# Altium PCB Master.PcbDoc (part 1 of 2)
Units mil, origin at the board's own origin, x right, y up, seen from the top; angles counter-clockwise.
Board outline 11420.03 x 8220.01 mil, 2 copper layers (Top Layer, Bottom Layer); 224 components, 0 nets, 1169 pads, 54 vias.
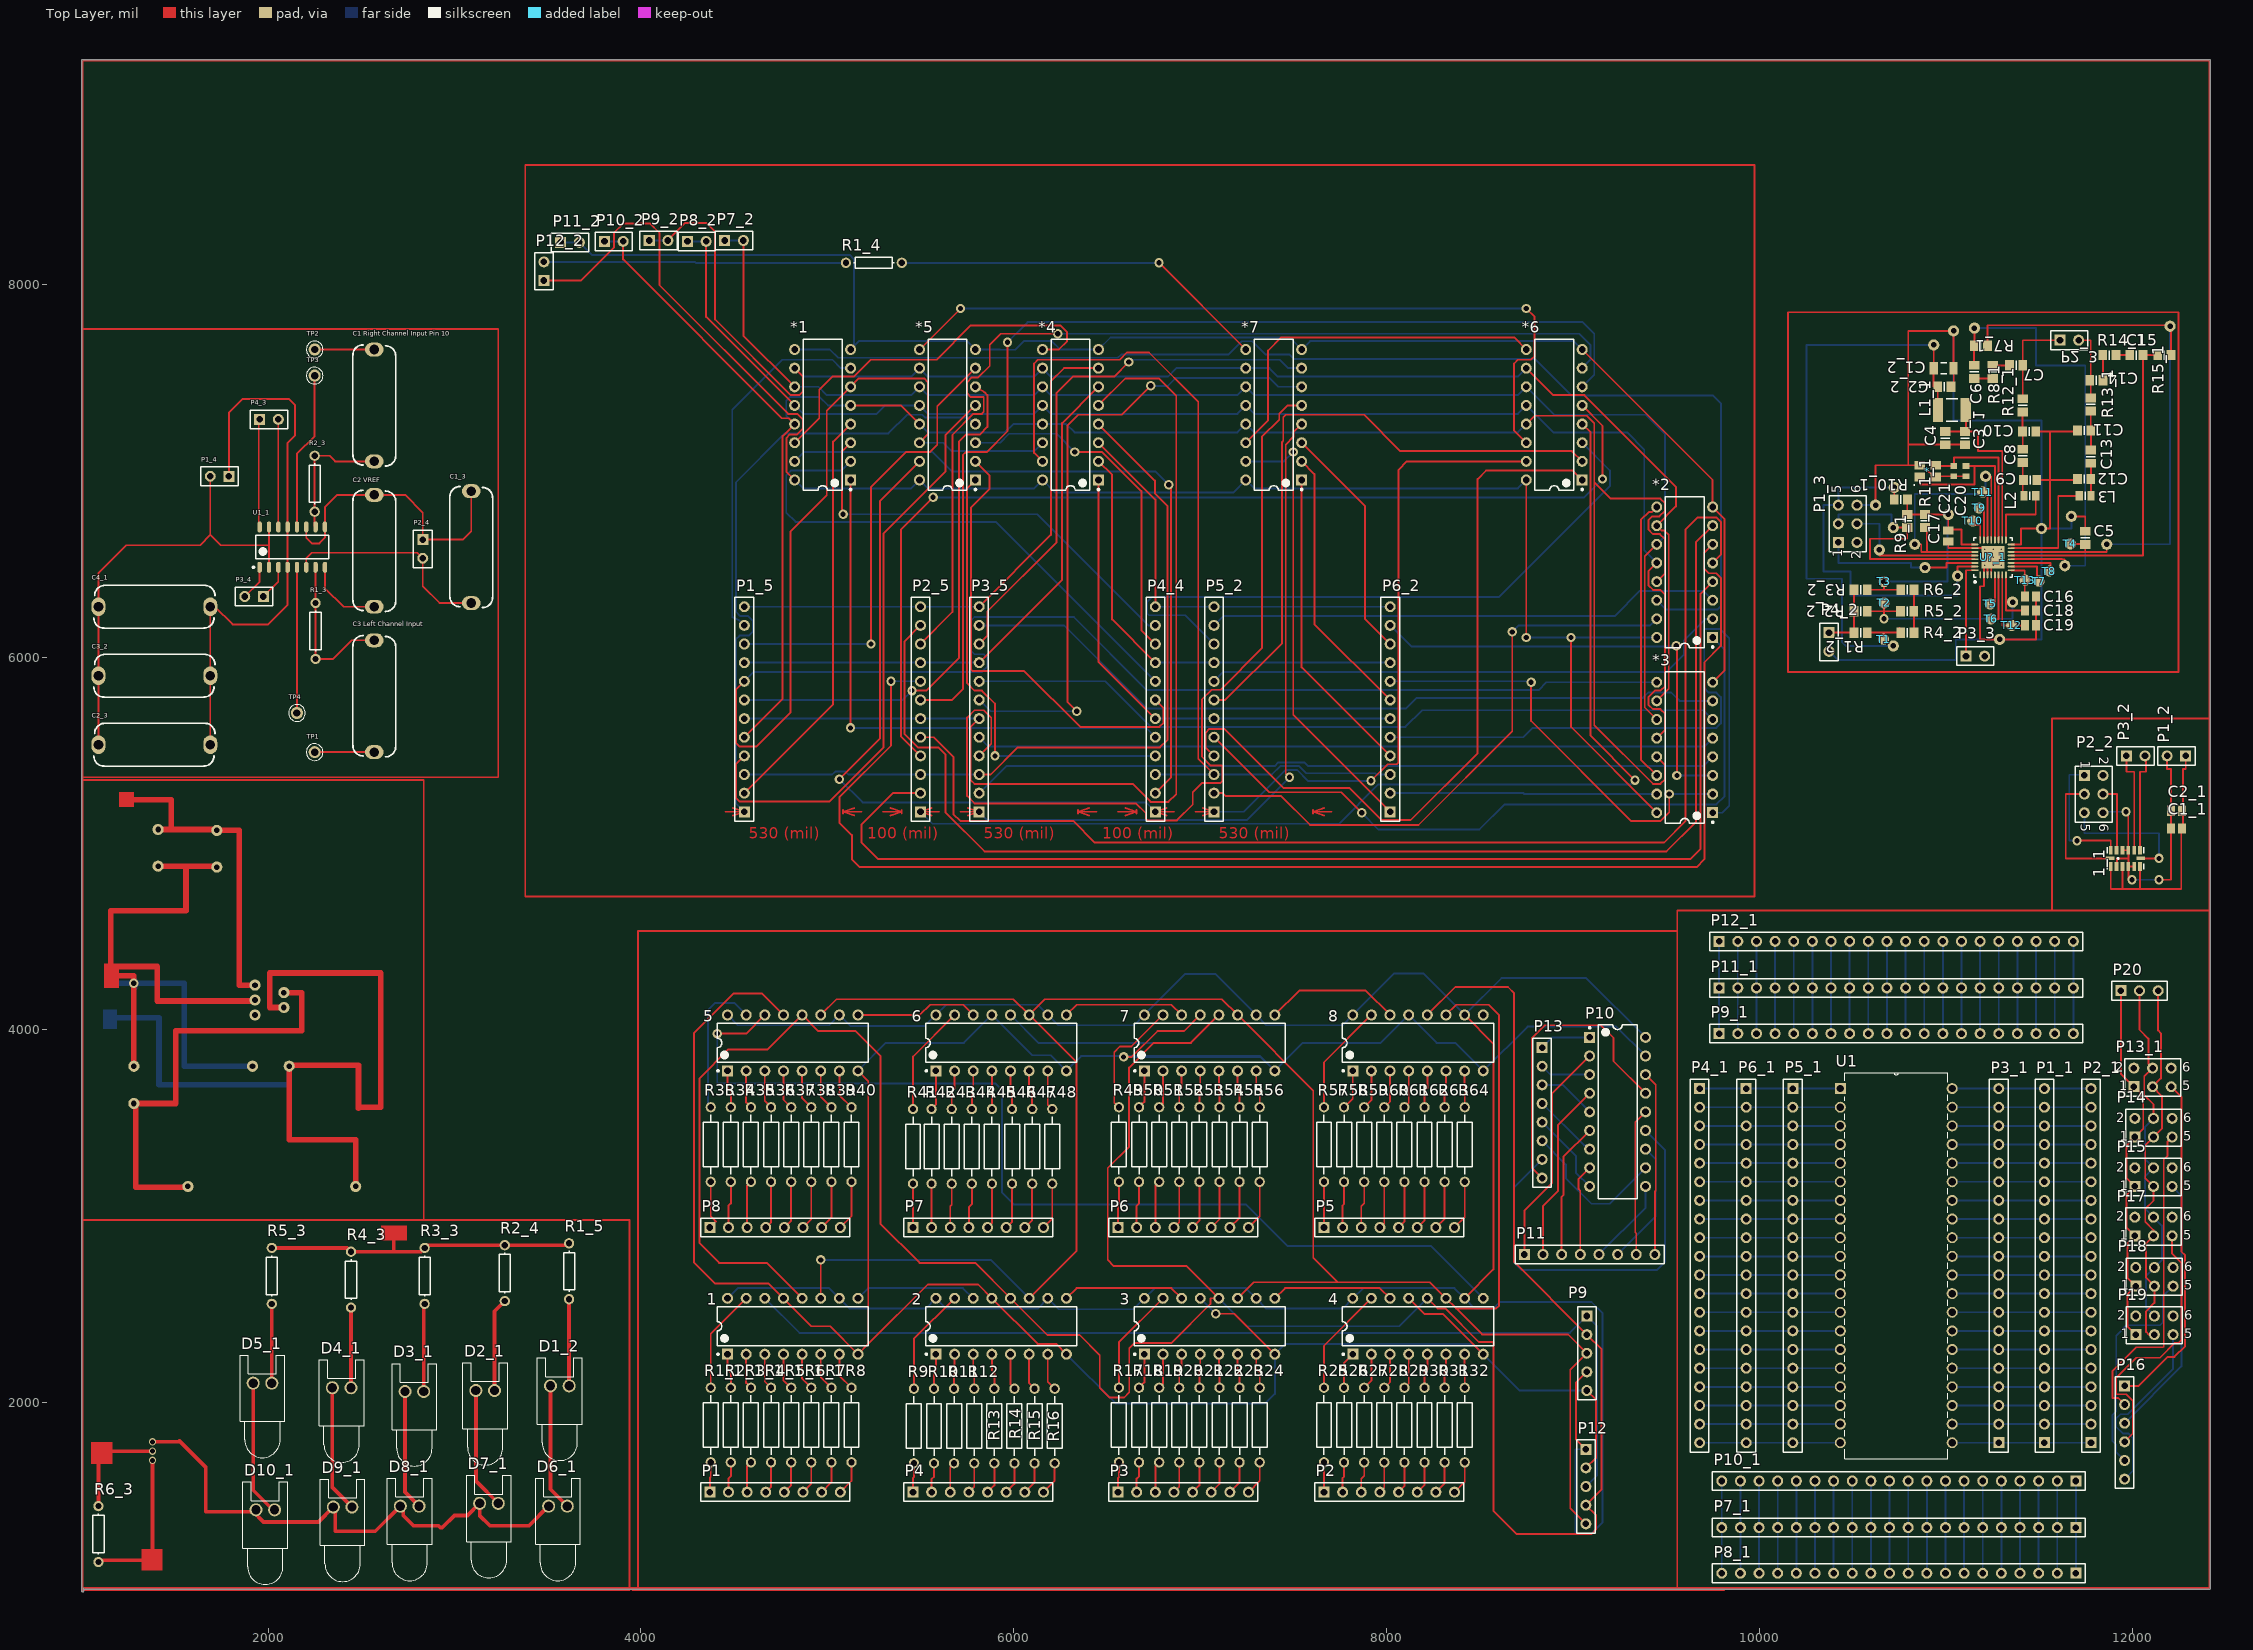
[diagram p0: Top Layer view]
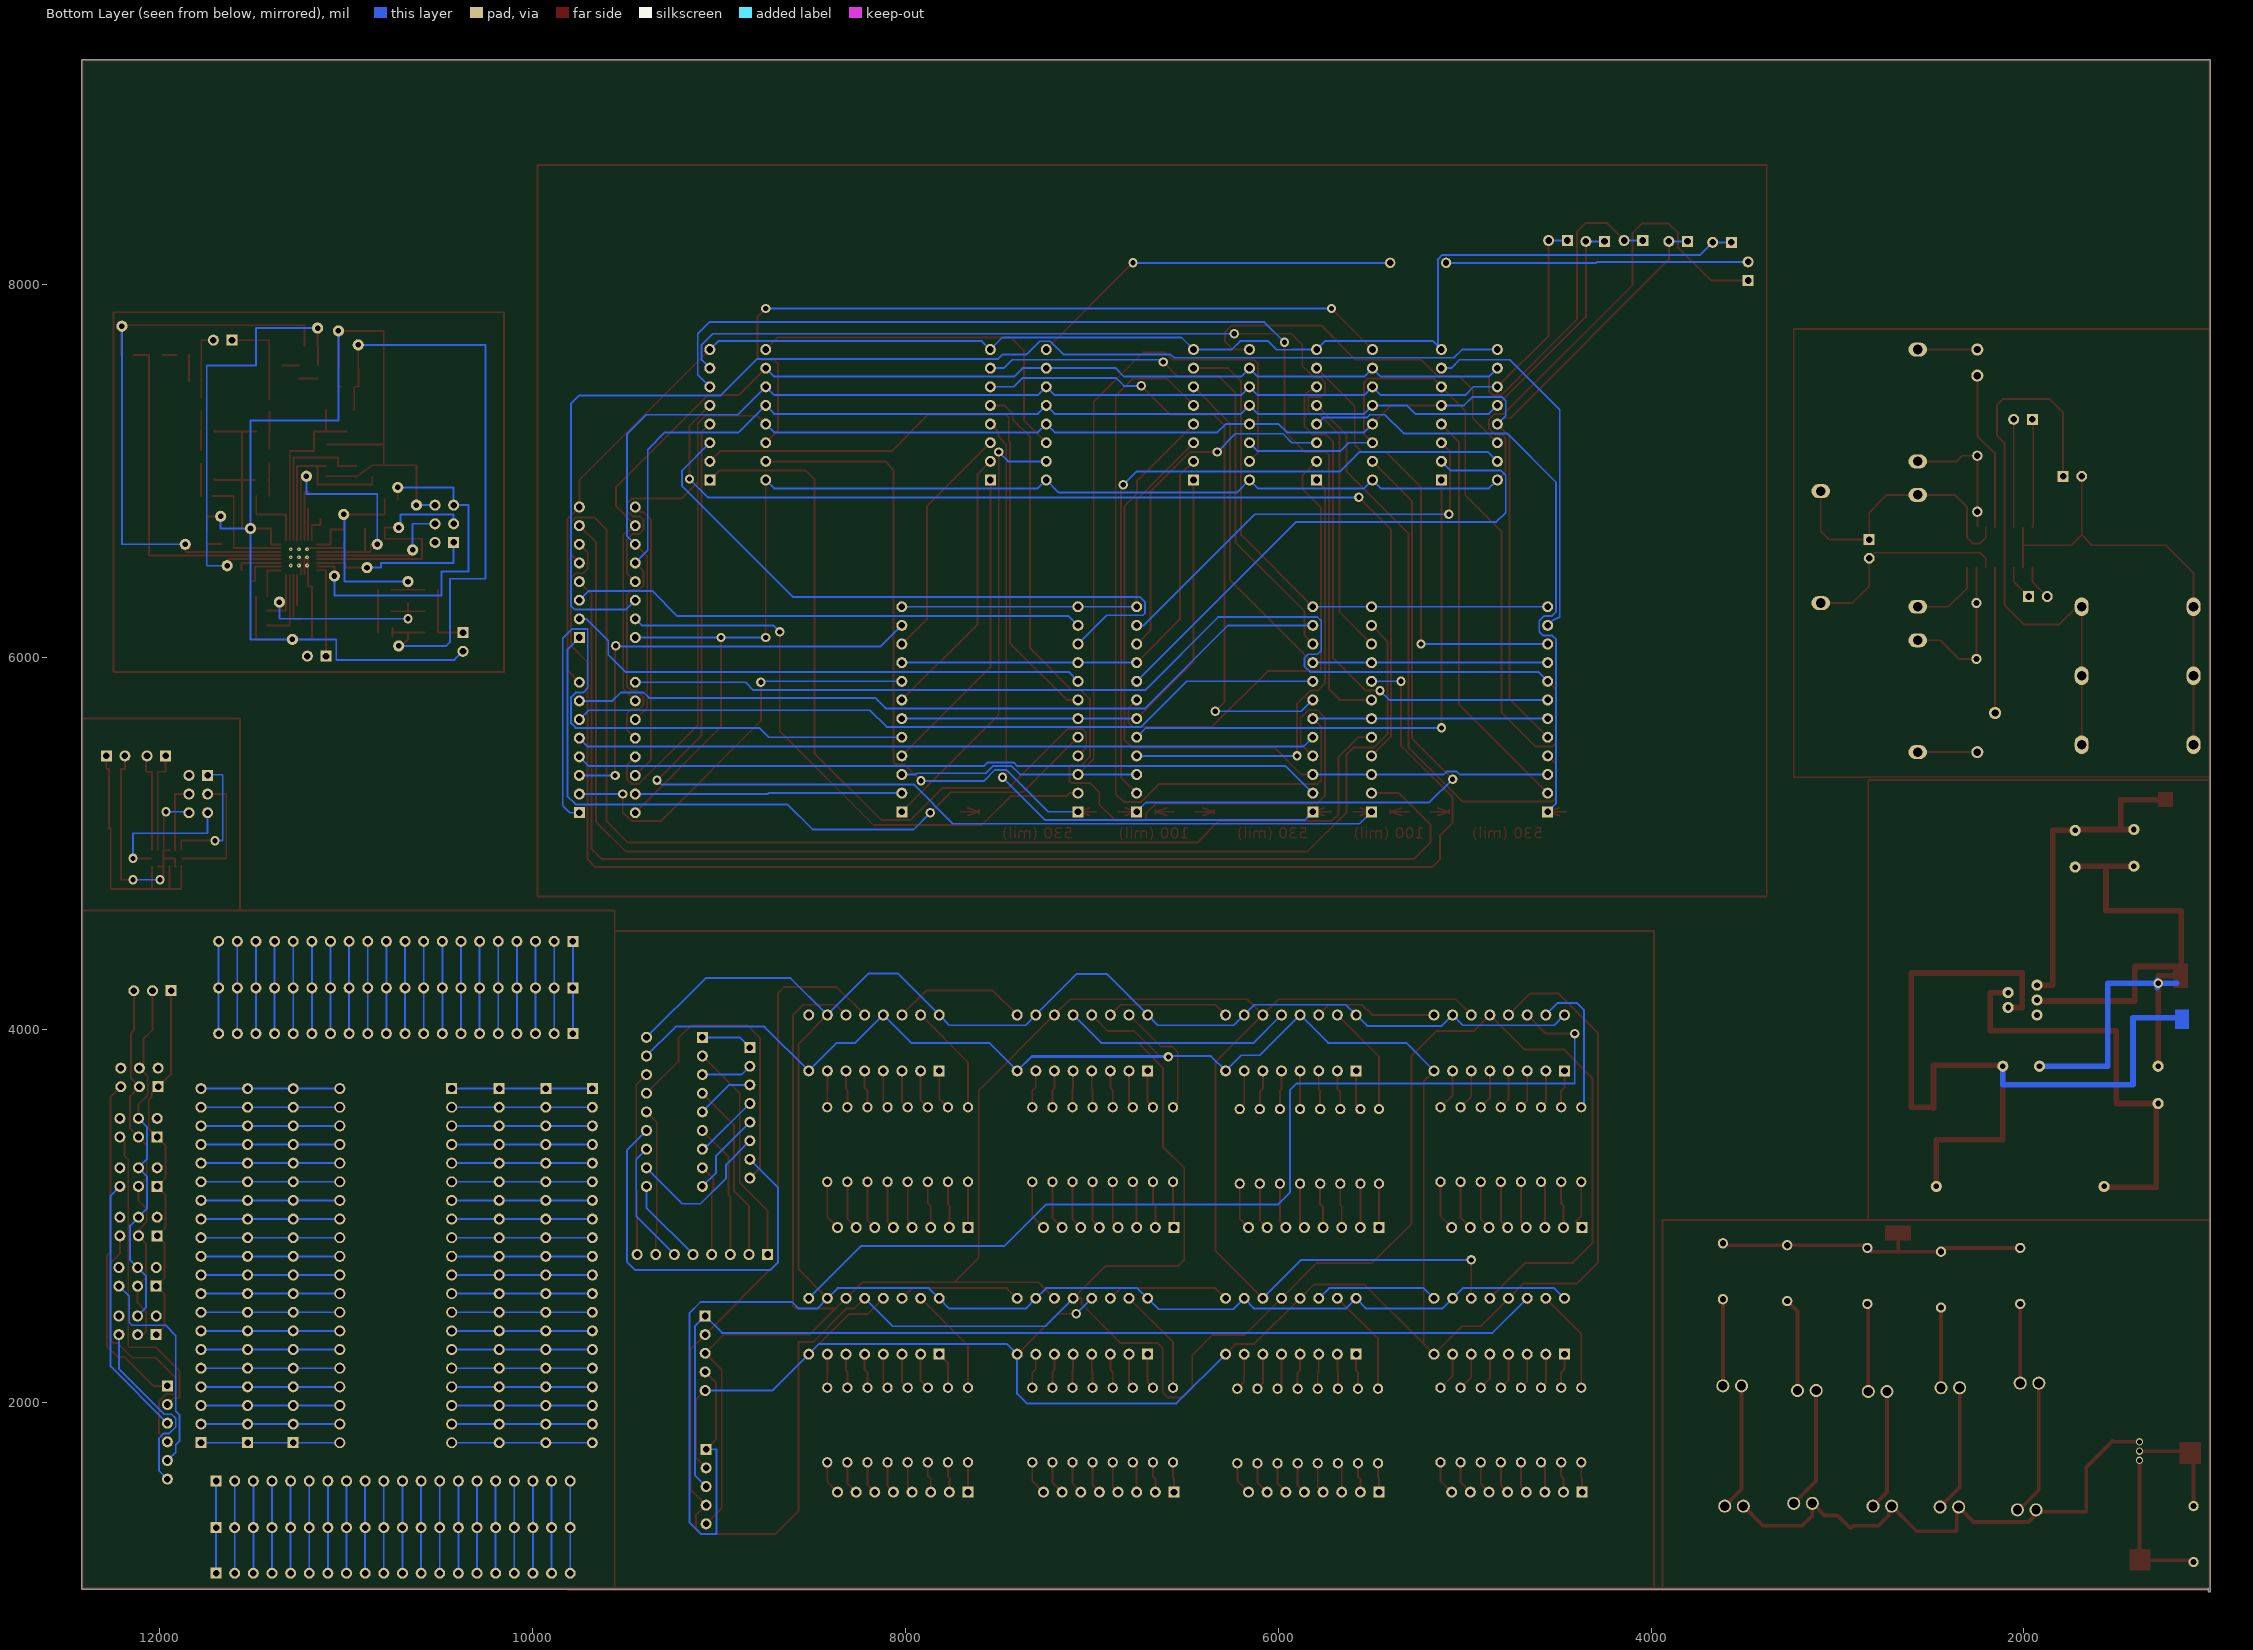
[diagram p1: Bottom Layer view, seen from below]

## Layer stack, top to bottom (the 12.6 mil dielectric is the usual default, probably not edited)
Top Solder: solder mask 0.4, Solder Resist, Dk 3.5
Top Layer: signal copper 1.4
Dielectric 1: dielectric 12.6, FR-4, Dk 4.8
Bottom Layer: signal copper 1.4
Bottom Solder: solder mask 0.4, Solder Resist, Dk 3.5

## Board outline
999.99,990 999.99,9200 cw(c1005,9200) 1005,9205.01 12415,9205.01 cw(c12415,9200) 12420.01,9200 12420.01,1005 cw(c12415,1005) 12415,999.99 1015,999.99 cw(c1015,1005) 1010.01,1004.45 1010.01,990 cw(c1005,990)

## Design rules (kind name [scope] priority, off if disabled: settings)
Clearance [All] p1: gap=10
PolygonConnect [All] p1: connectstyle=Relief reliefconductorwidth=10 reliefentries=4 polygonreliefangle="90 Angle" airgapwidth=10
RoomDefinition IRLED_1 [InComponentClass('IRLED')] p1: confinementstyle=ConfineIn formatcopy=TRUE lockcomponents=FALSE outline 1015,2980 3940,2980 3940,995 1015,995
RoomDefinition "Senior design LED matrix 3.0" [InComponentClass('Senior design LED matrix 3.0')] p2: confinementstyle=ConfineIn formatcopy=TRUE lockcomponents=FALSE outline 3385,4735 9985,4735 9985,8640.01 3385,8640.01
RoomDefinition "PAM 8403 Breakout Board" [InComponentClass('PAM 8403 Breakout Board')] p3: confinementstyle=ConfineIn formatcopy=TRUE lockcomponents=FALSE outline 3235,5360 3235,7760 1035,7760 1035,5360
RoomDefinition MCU [InComponentClass('MCU')] p4: confinementstyle=ConfineIn formatcopy=TRUE lockcomponents=FALSE outline 9610,1020 12415,1020 12415,4640 9610,4640
RoomDefinition CLRC663Design [InComponentClass('CLRC663Design')] p5: confinementstyle=ConfineIn formatcopy=TRUE lockcomponents=FALSE outline 12250.12,5920 12250.12,7850 10155,7850 10155,5920
RoomDefinition LEDCube [InComponentClass('LEDCube')] p6: confinementstyle=ConfineIn formatcopy=TRUE lockcomponents=FALSE outline 3985,995 9810,995 9810,4530 3985,4530
RoutingVias [All] p1: holewidth=28 width=50 viastyle="Through Hole" minholewidth=28 minwidth=50 maxholewidth=28 maxwidth=50
SolderMaskExpansion [All] p1: expansion=4
Width [All] p1: maxlimit=10 minlimit=10 preferedwidth=10
30 further rules are at their usual default settings.

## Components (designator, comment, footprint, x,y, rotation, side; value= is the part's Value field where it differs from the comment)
1 "74HC595" DIP-16 4815,2410 r90 top
1_1 "LIS302DL" LGA14_LIS302DL(Primary) 11964.25,4920 r180 top (schematic designator 1)
2 "74HC595" DIP-16 5933.1,2410 r90 top
3 "74HC595" DIP-16 7051.19,2410 r90 top
4 "74HC595" DIP-16 8169.29,2410 r90 top
5 "74HC595" DIP-16 4815,3930 r90 top
6 "74HC595" DIP-16 5933.1,3930 r90 top
7 "74HC595" DIP-16 7051.19,3930 r90 top
8 "74HC595" DIP-16 8169.29,3930 r90 top
* "Crystal" DFN220P355X80-4N 10904.25,6997.44 r0 top
*1 "Red_1" DIP-16 4975,7300 r180 top
*2 "Red_2" DIP-16 9600,6455 r180 top
*3 "Red_3" DIP-16 9600,5515 r180 top
*4 "Ground" DIP-16 6305,7300 r180 top
*5 "Green_1" DIP-16 5645,7300 r180 top
*6 "Green_2" DIP-16 8900,7300 r180 top
*7 "Green_3" DIP-16 7395,7300 r180 top
"C1 Right Channel Input Pin 10" "Cap" "Rad .6" 2570,7350 r90 top
C1_1 "Cap" C0805 12239.25,5080 r180 top (schematic designator C1)
C1_2 "Cap" C1206 10989.25,7550 r0 top (schematic designator C1)
C1_3 "Cap" "Rad .6" 3090,6590 r270 top (schematic designator C1)
"C2 VREF" "Cap" "Rad .6" 2570,6570 r90 top
C2_1 "Cap" C0805 12239.25,5175 r180 top (schematic designator C2)
C2_2 "Cap" 6-0805_N 10993.39,7450 r0 top (schematic designator C2)
C2_3 "Cap" "Rad .6" 1390,5530 r180 top (schematic designator C2)
"C3 Left Channel Input" "Cap" "Rad .6" 2570,5790 r270 top
C3_1 "Cap" 6-0805_N 11103.39,7175 r270 top (schematic designator C3)
C3_2 "Cap" "Rad .6" 1390,5900 r180 top (schematic designator C3)
C4 "Cap" 6-0805_N 10998.39,7175 r270 top
C4_1 "Cap" "Rad .6" 1390,6270 r180 top (schematic designator C4)
C5 "Cap" 6-0805_N 11749.25,6640 r90 top
C6 "Cap" 6-0805_N 11153.39,7530 r90 top
C7 "Cap" 6-0805_N 11378.39,7565 r0 top
C8 "Cap" 6-0805_N 11413.39,7080 r270 top
C9 "Cap" 6-0805_N 11453.39,6950 r180 top
C10 "Cap" 6-0805_N 11448.39,7210 r0 top
C11 "Cap" 6-0805_N 11743.39,7215 r0 top
C12 "Cap" 6-0805_N 11743.39,6955 r180 top
C13 "Cap" 6-0805_N 11778.39,7075 r270 top
C14 "Cap" 6-0805_N 11808.39,7485 r0 top
C15 "Cap" 6-0805_N 12023.39,7620 r0 top
C16 "Cap Pol3" C0805 11454.25,6325 r0 top
C17 "Cap Pol3" C0805 11014.25,6650 r270 top
C18 "Cap Pol3" C0805 11454.25,6250 r0 top
C19 "Cap Pol3" C0805 11454.25,6170 r0 top
C20 "Cap Semi" 1608[0603] 11109.25,6997.44 r90 top
C21 "Cap Semi" 1608[0603] 11044.25,6997.44 r90 top
D1_2 "LED0" LED-0 3565,2090 r0 top (schematic designator D1)
D2_1 "LED0" LED-0 3165,2065 r0 top (schematic designator D2)
D3_1 "LED0" LED-0 2785,2060 r0 top (schematic designator D3)
D4_1 "LED0" LED-0 2395,2080 r0 top (schematic designator D4)
D5_1 "LED0" LED-0 1970,2105 r0 top (schematic designator D5)
D6_1 "LED0" LED-0 3555,1445 r0 top (schematic designator D6)
D7_1 "LED0" LED-0 3185,1460 r0 top (schematic designator D7)
D8_1 "LED0" LED-0 2760,1445 r0 top (schematic designator D8)
D9_1 "LED0" LED-0 2400,1440 r0 top (schematic designator D9)
D10_1 "LED0" LED-0 1985,1425 r0 top (schematic designator D10)
L1_1 "Inductor" INDC4532 11033.39,7325 r180 top (schematic designator L1)
L2 "Inductor" 6-0805_L 11451.89,6865 r180 top
L3 "Inductor" 6-0805_L 11748.39,6865 r0 top
P1 "Header 8" HDR1X8 4370,1520 r0 top
P1_1 "Header 20" HDR1X20 11530,1785 r90 top (schematic designator P1)
P1_2 "Power" HDR1X2 12287.99,5470 r180 top (schematic designator P1)
P1_3 "SPI" HDR2X3#1 10424.25,6615 r90 top (schematic designator P1)
P1_4 "Header 2" HDR1X2 1790,6970 r180 top (schematic designator P1)
P1_5 "Header 12" HDR1X12 4555,5170 r90 top (schematic designator P1)
P2 "Header 8" HDR1X8 7665,1520 r0 top
P2_1 "Header 20" HDR1X20 11780,1785 r90 top (schematic designator P2)
P2_2 "SPI Header" HDR2X3#2 11744.25,5365 r270 top (schematic designator P2)
P2_3 "Header 2" HDR1X2 11613.39,7700 r0 top (schematic designator P2)
P2_4 "Header 2" HDR1X2 2830,6630 r270 top (schematic designator P2)
P2_5 "Header 12" HDR1X12 5500,5170 r90 top (schematic designator P2)
P3 "Header 8" HDR1X8 6560,1520 r0 top
P3_1 "Header 20" HDR1X20 11285,1785 r90 top (schematic designator P3)
P3_2 "Interrupt" HDR1X2 11969.25,5470 r0 top (schematic designator P3)
P3_3 "Interrupt" HDR1X2 11109.25,6005 r0 top (schematic designator P3)
P3_4 "Header 2" HDR1X2 1975,6325 r180 top (schematic designator P3)
P3_5 "Header 12" HDR1X12 5815,5170 r90 top (schematic designator P3)
P4 "Header 8" HDR1X8 5460,1520 r0 top
P4_1 "Header 20" HDR1X20 9680,3685 r270 top (schematic designator P4)
P4_2 "Power" HDR1X2 10374.25,6130.87 r270 top (schematic designator P4)
P4_3 "Header 2" HDR1X2 1955,7275 r0 top (schematic designator P4)
P4_4 "Header 12" HDR1X12 6760,5170 r90 top (schematic designator P4)
P5 "Header 8" HDR1X8 7665,2940 r0 top
P5_1 "Header 20" HDR1X20 10180,3685 r270 top (schematic designator P5)
P5_2 "Header 12" HDR1X12 7075,5170 r90 top (schematic designator P5)
P6 "Header 8" HDR1X8 6560,2940 r0 top
P6_1 "Header 20" HDR1X20 9930,3685 r270 top (schematic designator P6)
P6_2 "Header 12" HDR1X12 8020,5170 r90 top (schematic designator P6)
P7 "Header 8" HDR1X8 5460,2940 r0 top
P7_1 "Header 20" HDR1X20 11699,1330 r180 top (schematic designator P7)
P7_2 "11" HDR1X2 4450,8235 r0 top (schematic designator P7)
P8 "Header 8" HDR1X8 4370,2940 r0 top
P8_1 "Header 20" HDR1X20 11699,1085 r180 top (schematic designator P8)
P8_2 "12" HDR1X2 4250,8230 r0 top (schematic designator P8)
P9 "Header 5" HDR1X5 9075,2465 r270 top
P9_1 "Header 20" HDR1X20 9785,3980 r0 top (schematic designator P9)
P9_2 "10" HDR1X2 4045,8235 r0 top (schematic designator P9)
P10 "Darlinton transistorLeftToAVR" DIP-18 9240,3560 r0 top
P10_1 "Header 20" HDR1X20 11699,1580 r180 top (schematic designator P10)
P10_2 "13" HDR1X2 3805,8230 r0 top (schematic designator P10)
P11 "Cube Layer" HDR1X8 8740,2795 r0 top
P11_1 "Header 20" HDR1X20 9785,4225 r0 top (schematic designator P11)
P11_2 "Ground 8" HDR1X2 3570,8225 r0 top (schematic designator P11)
P12 "Matrix" HDR1X5 9070,1750 r270 top
P12_1 "Header 20" HDR1X20 9785,4475 r0 top (schematic designator P12)
P12_2 "1 (Power) 2 (Ground)" HDR1X2 3480,8020 r90 top (schematic designator P12)
P13 "AVR" HDR1X8 8835,3905 r270 top
P13_1 "Header 3X2" HDR2X3#2 12010,3695 r0 top (schematic designator P13)
P14 "Header 3X2" HDR2X3#2 12015,3425 r0 top
P15 "Header 3X2" HDR2X3#2 12015,3160 r0 top
P16 "Header 6" HDR1X6 11960,2090 r270 top
P17 "Header 3X2" HDR2X3#2 12015,2895 r0 top
P18 "Header 3X2" HDR2X3#2 12020,2625 r0 top
P19 "Header 3X2" HDR2X3#2 12020,2365 r0 top
P20 "Header 3" HDR1X3 11940,4210 r0 top
R1_1 "Res2" AXIAL-0.4 4374.88,1880 r270 top (schematic designator R1)
R1_2 "0R DNP" 6-0805_N 10544.25,6130.87 r180 top (schematic designator R1)
R1_3 "Res1" AXIAL-0.3 2255,6140 r90 top (schematic designator R1)
R1_4 "Res1" AXIAL-0.3 5250,8115 r180 top (schematic designator R1)
R1_5 "Res1" AXIAL-0.3 3615,2705 r90 top (schematic designator R1)
R2_1 "Res2" AXIAL-0.4 4482.76,1880 r270 top (schematic designator R2)
R2_2 "0R DNP" 6-0805_N 10544.25,6245.87 r180 top (schematic designator R2)
R2_3 "Res1" AXIAL-0.3 2250,6930 r270 top (schematic designator R2)
R2_4 "Res1" AXIAL-0.3 3270,2695 r90 top (schematic designator R2)
R3_1 "Res2" AXIAL-0.4 4590.63,1880 r270 top (schematic designator R3)
R3_2 "0R DNP" 6-0805_N 10544.25,6360.87 r180 top (schematic designator R3)
R3_3 "Res1" AXIAL-0.3 2840,2680 r90 top (schematic designator R3)
R4_1 "Res2" AXIAL-0.4 4698.5,1880 r270 top (schematic designator R4)
R4_2 "0R DNP" 6-0805_N 10794.25,6130.87 r180 top (schematic designator R4)
R4_3 "Res1" AXIAL-0.3 2445,2660 r90 top (schematic designator R4)
R5_1 "Res2" AXIAL-0.4 4806.38,1880 r270 top (schematic designator R5)
R5_2 "0R" 6-0805_N 10793.82,6245.87 r180 top (schematic designator R5)
R5_3 "Res1" AXIAL-0.3 2020,2680 r90 top (schematic designator R5)
R6_1 "Res2" AXIAL-0.4 4914.25,1880 r270 top (schematic designator R6)
R6_2 "0R" 6-0805_N 10794.25,6360.87 r180 top (schematic designator R6)
R6_3 "Res1" AXIAL-0.3 1090,1295 r90 top (schematic designator R6)
R7 "Res2" AXIAL-0.4 5022.13,1880 r270 top
R7_1 "Res3" 6-0805_N 11188.39,7670 r0 top (schematic designator R7)
R8 "Res2" AXIAL-0.4 5130,1880 r270 top
R8_1 "Res3" 6-0805_N 11253.39,7530 r90 top (schematic designator R8)
R9 "Res2" AXIAL-0.4 5464.88,1875 r270 top
R9_1 "Res3" 6-0805_N 10794.25,6730 r90 top (schematic designator R9)
R10 "Res2" AXIAL-0.4 5572.76,1875 r270 top
R10_1 "Res3" 6-0805_N 10759.25,6845 r0 top (schematic designator R10)
R11 "Res2" AXIAL-0.4 5680.63,1875 r270 top
R11_1 "Res3" 6-0805_N 10889.25,6730 r90 top (schematic designator R11)
R12 "Res2" AXIAL-0.4 5788.5,1875 r270 top
R12_1 "Res3" 6-0805_N 11413.39,7350 r90 top (schematic designator R12)
R13 "Res2" AXIAL-0.4 5896.38,1875 r270 top
R13_1 "Res3" 6-0805_N 11778.39,7355 r90 top (schematic designator R13)
R14 "Res2" AXIAL-0.4 6004.25,1875 r270 top
R14_1 "Res3" 6-0805_N 11878.39,7620 r180 top (schematic designator R14)
R15 "Res2" AXIAL-0.4 6112.13,1875 r270 top
R15_1 "Res3" 6-0805_N 12173.39,7620 r0 top (schematic designator R15)
R16 "Res2" AXIAL-0.4 6220,1875 r270 top
R17 "Res2" AXIAL-0.4 6564.88,1880 r270 top
R18 "Res2" AXIAL-0.4 6672.76,1880 r270 top
R19 "Res2" AXIAL-0.4 6780.63,1880 r270 top
R20 "Res2" AXIAL-0.4 6888.5,1880 r270 top
R21 "Res2" AXIAL-0.4 6996.38,1880 r270 top
R22 "Res2" AXIAL-0.4 7104.25,1880 r270 top
R23 "Res2" AXIAL-0.4 7212.13,1880 r270 top
R24 "Res2" AXIAL-0.4 7320,1880 r270 top
R25 "Res2" AXIAL-0.4 7664.88,1880 r270 top
R26 "Res2" AXIAL-0.4 7772.76,1880 r270 top
R27 "Res2" AXIAL-0.4 7880.63,1880 r270 top
R28 "Res2" AXIAL-0.4 7988.5,1880 r270 top
R29 "Res2" AXIAL-0.4 8096.38,1880 r270 top
R30 "Res2" AXIAL-0.4 8204.25,1880 r270 top
R31 "Res2" AXIAL-0.4 8312.13,1880 r270 top
R32 "Res2" AXIAL-0.4 8420,1880 r270 top
R33 "Res2" AXIAL-0.4 4374.88,3385 r90 top
R34 "Res2" AXIAL-0.4 4482.76,3385 r90 top
R35 "Res2" AXIAL-0.4 4590.63,3385 r90 top
R36 "Res2" AXIAL-0.4 4698.5,3385 r90 top
R37 "Res2" AXIAL-0.4 4806.38,3385 r90 top
R38 "Res2" AXIAL-0.4 4914.25,3385 r90 top
R39 "Res2" AXIAL-0.4 5022.13,3385 r90 top
R40 "Res2" AXIAL-0.4 5130,3385 r90 top
R41 "Res2" AXIAL-0.4 5460,3375 r90 top
R42 "Res2" AXIAL-0.4 5559.88,3375 r90 top
R43 "Res2" AXIAL-0.4 5667.76,3375 r90 top
R44 "Res2" AXIAL-0.4 5775.63,3375 r90 top
R45 "Res2" AXIAL-0.4 5883.5,3375 r90 top
R46 "Res2" AXIAL-0.4 5991.38,3375 r90 top
R47 "Res2" AXIAL-0.4 6099.25,3375 r90 top
R48 "Res2" AXIAL-0.4 6207.13,3375 r90 top
R49 "Res2" AXIAL-0.4 6564.88,3385 r90 top
R50 "Res2" AXIAL-0.4 6672.76,3385 r90 top
R51 "Res2" AXIAL-0.4 6780.63,3385 r90 top
R52 "Res2" AXIAL-0.4 6888.5,3385 r90 top
R53 "Res2" AXIAL-0.4 6996.38,3385 r90 top
R54 "Res2" AXIAL-0.4 7104.25,3385 r90 top
R55 "Res2" AXIAL-0.4 7212.13,3385 r90 top
R56 "Res2" AXIAL-0.4 7320,3385 r90 top
R57 "Res2" AXIAL-0.4 7664.88,3385 r90 top
R58 "Res2" AXIAL-0.4 7772.76,3385 r90 top
R59 "Res2" AXIAL-0.4 7880.63,3385 r90 top
R60 "Res2" AXIAL-0.4 7988.5,3385 r90 top
R61 "Res2" AXIAL-0.4 8096.38,3385 r90 top
R62 "Res2" AXIAL-0.4 8204.25,3385 r90 top
R63 "Res2" AXIAL-0.4 8312.13,3385 r90 top
R64 "Res2" AXIAL-0.4 8420,3385 r90 top
T1 "TVDD" PCBComponent_1 60281.75,55780.87 r0 top
T2 "VDD" PCBComponent_1 60284.68,55975.87 r0 top
T3 "PVDD" PCBComponent_1 60284.68,56090.87 r0 top
T4 "VMID" PCBComponent_1 -37945.75,-43077.56 r180 top
T5 "SIGIN" PCBComponent_1 -38375.75,-43400 r180 top
T6 "SIGOUT" PCBComponent_1 60928.39,-43410.43 r270 top
T7 "AUX1" PCBComponent_1 -38184.02,56022.44 r90 top
T8 "AUX2" PCBComponent_1 -38058.19,-43223.27 r180 top
T9 "SCL2" PCBComponent_1 -38504.88,56415 r90 top
T10 "SDA2" PCBComponent_1 -38469.88,-42955 r180 top locked
T11 "CLCKOUT" PCBComponent_1 -38485.75,56500 r90 top
T12 "DVDD" PCBComponent_1 -38330.75,55785 r90 top
T13 "AVDD" PCBComponent_1 -38189.02,-43272.13 r180 top locked
TP1 "TESTPOINT" "THROUGH HOLE TP" 2250,5490 r90 top
TP2 "TESTPOINT" "THROUGH HOLE TP" 2250,7650 r90 top
TP3 "TESTPOINT" "THROUGH HOLE TP" 2250,7510 r90 top
TP4 "TESTPOINT" "THROUGH HOLE TP" 2155,5700 r90 top
U1 "ATMEGA1284P-PU" DIP254P1524X483-40_ATMEGA1284P-PU(Primary) 11035,1785 r0 top
U1_1 "PAM8403" SOP127P600X175-16N 2130,6590 r90 top (schematic designator U1)
U?_1 "CLRC663" QFN50P500X500X100_HS-33N 11254.25,6535 r90 top (schematic designator U?)

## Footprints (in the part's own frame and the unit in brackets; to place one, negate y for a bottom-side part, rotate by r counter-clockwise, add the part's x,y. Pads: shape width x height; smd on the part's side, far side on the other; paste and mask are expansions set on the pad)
6-0805_L [mm] "Chip Resistor, Body 2.0x1.2mm, IPC High Density"
  rect 1x1.3 smd: 1(-0.8,0) 2(0.8,0)
  silkscreen extent 0,-0.55 0,0.55, body extent -1.07,-0.7 1.07,0.7, height 0.7
6-0805_N [mm] "Chip Resistor, Body 2.0x1.2mm, IPC Medium Density"
  rect 1.2x1.4 smd: 1(-0.9,0) 2(0.9,0)
  silkscreen extent 0,-0.6 0,0.6, body extent -1.07,-0.7 1.07,0.7, height 0.7
1608[0603] [mm] "Chip Capacitor, Body 1.6x0.8mm, IPC High Density"
  rect 0.8x0.9 smd: 1(-0.7,0) 2(0.7,0)
  body extent -0.87,-0.48 0.87,0.48, height 1.3
AXIAL-0.3 [mm] "Axial Device, Thru-Hole; 2 Leads; 0.3 in Pin Spacing"
  round 1.4 hole 0.85: 1(-3.81,0) 2(3.81,0)
  silkscreen extent -2.77,-0.76 2.77,0.76
AXIAL-0.4 [mm] "Axial Device, Thru-Hole; 2 Leads; 0.4 in Pin Spacing"
  round 1.4 hole 0.85: 1(-5.08,0) 2(5.08,0)
  silkscreen extent -4.06,-1.02 4.06,1.02
C0805 [mm] "Chip Capacitor, Body 2.0x1.3mm, IPC High Density"
  rect 1.1x1.4 smd: 1(-0.75,0) 2(0.75,0)
  body extent -1.1,-0.72 1.1,0.72, height 1.4
C1206 [mm] "Chip Capacitor, Body 3.2x1.6mm, IPC High Density"
  rect 1.1x1.7 smd: 1(-1.35,0) 2(1.35,0)
  silkscreen extent -0.4,-0.75 0.4,0.75, body extent -1.7,-0.9 1.7,0.9, height 1.3
DFN220P355X80-4N [mm] "DFN, 4-Leads, Body 2.90x3.55mm, Pitch 2.20mm, IPC Medium Density"
  rect 1.4x1.2 smd: 1(-1.1,-0.8) 2(-1.1,0.8) 3(1.1,0.8) 4(1.1,-0.8)
  silkscreen extent -1.9,-1.95 -1.8,-1.85, body extent -1.85,-1.5 1.85,1.5, height 0.8
DIP254P1524X483-40_ATMEGA1284P-PU(Primary) [mil]
  rect 59x59 hole 39 mask-1000: 1(-600,1900)
  round 59 hole 39 mask-1000: 2(-600,1800) 3(-600,1700) 4(-600,1600) 5(-600,1500) 6(-600,1400) 7(-600,1300) 9(-600,1100) 10(-600,1000) 11(-600,900) 12(-600,800) 13(-600,700) 14(-600,600) 15(-600,500) 16(-600,400) 17(-600,300) 18(-600,200) 19(-600,100) 20(-600,0) 21(0,0) 22(0,100) 23(0,200) 24(0,300) 25(0,400) 26(0,500) 27(0,600) 28(0,700) 29(0,800) 30(0,900) 31(0,1000) 32(0,1100) 33(0,1200) 34(0,1300) 35(0,1400) 36(0,1500) 37(0,1600) 38(0,1700) 39(0,1800) 40(0,1900)
  round 59 hole 39: 8(-600,1200)
  silkscreen extent -575,-85 -25,1985
DIP-16 [mm] "DIP; 16 Leads; Row Spacing 7.62 mm; Pitch 2.54 mm"
  rect 1.5x1.5 hole 0.9: 1(-3.81,8.89)
  round 1.5 hole 0.9: 2(-3.81,6.35) 3(-3.81,3.81) 4(-3.81,1.27) 5(-3.81,-1.27) 6(-3.81,-3.81) 7(-3.81,-6.35) 8(-3.81,-8.89) 9(3.81,-8.89) 10(3.81,-6.35) 11(3.81,-3.81) 12(3.81,-1.27) 13(3.81,1.27) 14(3.81,3.81) 15(3.81,6.35) 16(3.81,8.89)
  silkscreen extent -3.93,-10.3 2.65,10.31, body extent -3.6,-10.28 3.6,10.28, height 5.08
DIP-18 [mm] "DIP; 18 Leads; Row Spacing 7.62 mm; Pitch 2.54 mm"
  rect 1.5x1.5 hole 0.9: 1(-3.81,10.16)
  round 1.5 hole 0.9: 2(-3.81,7.62) 3(-3.81,5.08) 4(-3.81,2.54) 5(-3.81,0) 6(-3.81,-2.54) 7(-3.81,-5.08) 8(-3.81,-7.62) 9(-3.81,-10.16) 10(3.81,-10.16) 11(3.81,-7.62) 12(3.81,-5.08) 13(3.81,-2.54) 14(3.81,0) 15(3.81,2.54) 16(3.81,5.08) 17(3.81,7.62) 18(3.81,10.16)
  silkscreen extent -3.93,-11.85 2.65,11.85, body extent -3.6,-11.8 3.6,11.8, height 5.08
HDR1X2 [mm] "Connector; Header; 2 Position"
  rect 1.5x1.5 hole 0.9: 1(0,0)
  round 1.5 hole 0.9: 2(2.54,0)
  silkscreen extent -1.27,-1.27 3.81,1.27
HDR1X3 [mm] "Connector; Header; 3 Position"
  rect 1.5x1.5 hole 0.9: 1(0,0)
  round 1.5 hole 0.9: 2(2.54,0) 3(5.08,0)
  silkscreen extent -1.27,-1.27 6.35,1.27
HDR1X5 [mm] "Connector; Header; 5 Position"
  rect 1.5x1.5 hole 0.9: 1(0,0)
  round 1.5 hole 0.9: 2(2.54,0) 3(5.08,0) 4(7.62,0) 5(10.16,0)
  silkscreen extent -1.27,-1.27 11.43,1.27
HDR1X6 [mm] "Connector; Header; 6 Position"
  rect 1.5x1.5 hole 0.9: 1(0,0)
  round 1.5 hole 0.9: 2(2.54,0) 3(5.08,0) 4(7.62,0) 5(10.16,0) 6(12.7,0)
  silkscreen extent -1.27,-1.27 13.97,1.27
HDR1X8 [mm] "Connector; Header; 8 Position"
  rect 1.5x1.5 hole 0.9: 1(0,0)
  round 1.5 hole 0.9: 2(2.54,0) 3(5.08,0) 4(7.62,0) 5(10.16,0) 6(12.7,0) 7(15.24,0) 8(17.78,0)
  silkscreen extent -1.27,-1.27 19.05,1.27
HDR1X12 [mm] "Connector; Header; 12 Position"
  rect 1.5x1.5 hole 0.9: 1(0,0)
  round 1.5 hole 0.9: 2(2.54,0) 3(5.08,0) 4(7.62,0) 5(10.16,0) 6(12.7,0) 7(15.24,0) 8(17.78,0) 9(20.32,0) 10(22.86,0) 11(25.4,0) 12(27.94,0)
  silkscreen extent -1.27,-1.27 29.21,1.27
HDR1X20 [mm] "Connector; Header; 20 Position"
  rect 1.5x1.5 hole 0.9: 1(0,0)
  round 1.5 hole 0.9: 2(2.54,0) 3(5.08,0) 4(7.62,0) 5(10.16,0) 6(12.7,0) 7(15.24,0) 8(17.78,0) 9(20.32,0) 10(22.86,0) 11(25.4,0) 12(27.94,0) 13(30.48,0) 14(33.02,0) 15(35.56,0) 16(38.1,0) 17(40.64,0) 18(43.18,0) 19(45.72,0) 20(48.26,0)
  silkscreen extent -1.27,-1.27 49.53,1.27
HDR2X3#1 [mm] "Connector; Header; 3x2 Position"
  rect 1.5x1.5 hole 0.9: 1(0,0)
  round 1.5 hole 0.9: 2(0,-2.54) 3(2.54,0) 4(2.54,-2.54) 5(5.08,0) 6(5.08,-2.54)
  silkscreen extent -1.27,-3.81 6.35,1.27
HDR2X3#2 [mm] "Connector; Header; 3x2 Position"
  rect 1.5x1.5 hole 0.9: 1(0,0)
  round 1.5 hole 0.9: 2(0,2.54) 3(2.54,0) 4(2.54,2.54) 5(5.08,0) 6(5.08,2.54)
  silkscreen extent -1.27,-1.27 6.35,3.81
INDC4532 [mm] "Chip Inductor, Body 4.5x3.2mm, IPC High Density"
  rect 1.4x3.3 smd: 1(-1.9,0) 2(1.9,0)
  silkscreen extent -0.8,-1.55 0.8,1.55, body extent -2.4,-1.7 2.4,1.7, height 0.55
LED-0 [mil] "LED; 2 Leads"
  round 70 hole 50: 1(50,0) 2(-50,0)
  silkscreen extent -120,-400 120,150
LGA14_LIS302DL(Primary) [mm]
  rect 0.5x1.2 smd paste-25.4 mask-25.4: 1(2,1.1) 2(1.2,1.1) 3(0.4,1.1) 4(-0.4,1.1) 5(-1.2,1.1) 6(-2,1.1) 8(-2,-1.1) 9(-1.2,-1.1) 10(-0.4,-1.1) 11(0.4,-1.1) 12(1.2,-1.1) 13(2,-1.1)
  rect 1.2x0.5 smd paste-25.4 mask-25.4: 7(-2.1,0) 14(2.1,0)
  silkscreen extent -2.5,-1.5 2.5,1.5
PCBComponent_1 [mil]
  round 60 smd: 1(-49615,-49685)
QFN50P500X500X100_HS-33N [mm] "QFN, 32-Leads, Body 5.00x5.00mm, Pitch 0.50mm, Thermal Pad 3.10x3.10mm, IPC Medium Density"
  oval 0.95x0.25 smd: 1(-2.375,1.75) 2(-2.375,1.25) 3(-2.375,0.75) 4(-2.375,0.25) 5(-2.375,-0.25) 6(-2.375,-0.75) 7(-2.375,-1.25) 8(-2.375,-1.75) 17(2.375,-1.75) 18(2.375,-1.25) 19(2.375,-0.75) 20(2.375,-0.25) 21(2.375,0.25) 22(2.375,0.75) 23(2.375,1.25) 24(2.375,1.75)
  oval 0.25x0.95 smd: 9(-1.75,-2.475) 10(-1.25,-2.475) 11(-0.75,-2.475) 12(-0.25,-2.475) 13(0.25,-2.475) 14(0.75,-2.475) 15(1.25,-2.475) 16(1.75,-2.475) 25(1.75,2.475) 26(1.25,2.475) 27(0.75,2.475) 28(0.25,2.475) 29(-0.25,2.475) 30(-0.75,2.475) 31(-1.25,2.475) 32(-1.75,2.475)
  rect 3.1x3.1 smd: 33(0,0)
  silkscreen extent -3.47,-2.6 2.7,2.6, body extent -2.55,-2.45 2.55,2.45, height 1
"Rad .6" [mil] "Radial"
  oval 75x100 hole 52: 1(-300,0) 2(300,0)
  silkscreen extent -325,-115 325,115
SOP127P600X175-16N [mm] "SOP, 16-Leads, Body 9.90x3.90mm, Pitch 1.27mm, IPC Medium Density"
  oval 1.5x0.6 smd: 1(-2.75,4.445) 2(-2.75,3.175) 3(-2.75,1.905) 4(-2.75,0.635) 5(-2.75,-0.635) 6(-2.75,-1.905) 7(-2.75,-3.175) 8(-2.75,-4.445) 9(2.75,-4.445) 10(2.75,-3.175) 11(2.75,-1.905) 12(2.75,-0.635) 13(2.75,0.635) 14(2.75,1.905) 15(2.75,3.175) 16(2.75,4.445)
  silkscreen extent -2.87,-5 1.6,5.42, body extent -2,-5 2,5, height 1.75
"THROUGH HOLE TP" [mil]
  round 65 hole 40: 1(0,0)
  silkscreen extent -45,-45 45,45

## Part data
1 2 3 4 5 6 7 8 * *1 *2 *3 *4 *5 *6 *7: library part Component_1
"C1 Right Channel Input Pin 10" C1_2 C1_3 "C2 VREF" C2_2 C2_3 "C3 Left Channel Input" C3_1 C3_2 C4 C4_1 C5 C6 C7 C8 C9 C10 C11 C12 C13 C14 C15: "Capacitor"
C1_1 C2_1: library part "Cap Pol3", "Polarized Capacitor (Surface Mount)"
C16 C17 C18 C19: "Polarized Capacitor (Surface Mount)"
C20 C21: "Capacitor (Semiconductor SIM Model)"
D1_2 D2_1 D3_1 D4_1 D5_1 D6_1 D7_1 D8_1 D9_1 D10_1: "Typical INFRARED GaAs LED"
P1 P2 P3 P4 P5 P6 P7 P8: "Header, 8-Pin"
P1_1 P2_1 P3_1 P4_1 P5_1 P6_1 P7_1 P8_1 P9_1 P10_1 P11_1 P12_1: "Header, 20-Pin"
P1_2 P3_2 P3_3 P4_2 P7_2 P8_2 P9_2 P10_2 P11_2 P12_2: library part "Header 2", "Header, 2-Pin"
P1_3 P2_2: library part "Header 3X2", "Header, 3-Pin, Dual row"
P1_4 P2_3 P2_4 P3_4 P4_3: "Header, 2-Pin"
P1_5 P2_5 P3_5 P4_4 P5_2 P6_2: "Header, 12-Pin"
P9: "Header, 5-Pin"
P10: library part "Header 9X2", "Header, 9-Pin, Dual row"
P11 P13: library part "Header 8", "Header, 8-Pin"
P12: library part "Header 5", "Header, 5-Pin"
P13_1 P14 P15 P17 P18 P19: "Header, 3-Pin, Dual row"
P16: "Header, 6-Pin"
P20: "Header, 3-Pin"
R1_1 R1_3 R1_4 R1_5 R2_1 R2_3 R2_4 R3_1 R3_3 R4_1 R4_3 R5_1 R5_3 R6_1 R6_3 R7 R7_1 R8 R8_1 R9 R9_1 R10 R10_1 R11 R11_1 R12 R12_1 R13 R13_1 R14 R14_1 R15 R15_1 R16 R17 R18 R19 R20 R21 R22 R23 R24 R25 R26 R27 R28 R29 R30 R31 R32 R33 R34 R35 R36 R37 R38 R39 R40 R41 R42 R43 R44 R45 R46 R47 R48 R49 R50 R51 R52 R53 R54 R55 R56 R57 R58 R59 R60 R61 R62 R63 R64: "Resistor"
R1_2 R2_2 R3_2 R4_2 R5_2 R6_2: library part RESC0805, "RESC0805"
T1 T2 T3 T4 T5 T6 T7 T8 T9 T10 T11 T12 T13: library part Testpoint
TP1 TP2 TP3 TP4: library part TESTPOINT_2, "Through Hole Test Point"
U1_1: "PAM8403 Ausio Amplifier"

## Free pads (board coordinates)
  round 60 hole 30: 9(11214.25,6970) 10(11359.25,6295) 13(11639.25,6490) 14(11154.25,7765) 15(11514.25,6690) 16(10936.1,7675) 18(11064.25,6435) 19(10889.25,6480) 22(11864.25,6605) 23(12204.25,7775) 24(11674.25,6755) 25(11289.25,6095) 26(10644.25,6575) 27(11014.25,6765.43) 28(10669.25,6405) 29(10719.25,6060) 30(10724.25,6910) 31(10719.25,6694.57) 33(10624.25,6815) 35(11042.4,7750) 36(10834.25,6605) 37(1930,4240) 38(2085,4200) 39(2085,4120) 40(1930,4080) 41(1930,4160) 42(1570,3160) 43(2470,3160) 44(1725,5070) 45(1725,4873.15) 46(1410,4878.15) 47(1410,5075) 48(1916.57,3805) 49(2113.43,3805) 50(1280,3805) 51(1280,3605)

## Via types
v1: diameter 50, hole 28, Top Layer to Bottom Layer, 42 vias
v2: diameter 19.68, hole 7.87, Top Layer to Bottom Layer, 9 vias
v3: diameter 40, hole 27, Top Layer to Bottom Layer, 3 vias

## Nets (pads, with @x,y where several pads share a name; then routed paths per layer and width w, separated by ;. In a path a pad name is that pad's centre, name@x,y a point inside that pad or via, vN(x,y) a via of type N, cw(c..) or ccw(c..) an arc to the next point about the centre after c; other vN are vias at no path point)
pads on no net: 1.1 1.2 1.3 1.4 1.5 1.6 1.7 1.8 1.9 1.10 1.11 1.12 1.13 1.14 1.15 1.16 1_1.1 1_1.2 1_1.3 1_1.4 1_1.5 1_1.6 1_1.7 1_1.8 1_1.9 1_1.10 1_1.11 1_1.12 1_1.13 1_1.14 2.1 2.2 2.3 2.4 2.5 2.6 2.7 2.8 2.9 2.10 2.11 2.12 2.13 2.14 2.15 2.16 3.1 3.2 3.3 3.4 3.5 3.6 3.7 3.8 3.9 3.10 3.11 3.12 3.13 3.14 3.15 3.16 4.1 4.2 4.3 4.4 4.5 4.6 4.7 4.8 4.9 4.10 4.11 4.12 4.13 4.14 4.15 4.16 5.1 5.2 5.3 5.4 5.5 5.6 5.7 5.8 5.9 5.10 5.11 5.12 5.13 5.14 5.15 5.16 6.1 6.2 6.3 6.4 6.5 6.6 6.7 6.8 6.9 6.10 6.11 6.12 6.13 6.14 6.15 6.16 7.1 7.2 7.3 7.4 7.5 7.6 7.7 7.8 7.9 7.10 7.11 7.12 7.13 7.14 7.15 7.16 8.1 8.2 8.3 8.4 8.5 8.6 8.7 8.8 8.9 8.10 8.11 8.12 8.13 8.14 8.15 8.16 "C1 Right Channel Input Pin 10.1" "C1 Right Channel Input Pin 10.2" "C2 VREF.1" "C2 VREF.2" "C3 Left Channel Input.1" "C3 Left Channel Input.2" *1.1 *1.2 *1.3 *1.4 *1.5 *1.6 *1.7 *1.8 *1.9 *1.10 *1.11 *1.12 *1.13 *1.14 *1.15 *1.16 *2.1 *2.2 *2.3 *2.4 *2.5 *2.6 *2.7 *2.8 *2.9 *2.10 *2.11 *2.12 *2.13 *2.14 *2.15 *2.16 *3.1 *3.2 *3.3 *3.4 *3.5 *3.6 *3.7 *3.8 *3.9 *3.10 *3.11 *3.12 *3.13 *3.14 *3.15 *3.16 *4.1 *4.2 *4.3 *4.4 *4.5 *4.6 *4.7 *4.8 *4.9 *4.10 *4.11 *4.12 *4.13 *4.14 *4.15 *4.16 *5.1 *5.2 *5.3 *5.4 *5.5 *5.6 *5.7 *5.8 *5.9 *5.10 *5.11 *5.12 *5.13 *5.14 *5.15 *5.16 *6.1 *6.2 *6.3 *6.4 *6.5 *6.6 *6.7 *6.8 *6.9 *6.10 *6.11 *6.12 *6.13 *6.14 *6.15 *6.16 *7.1 *7.2 *7.3 *7.4 *7.5 *7.6 *7.7 *7.8 *7.9 *7.10 *7.11 *7.12 *7.13 *7.14 *7.15 *7.16 *.1 *.2 *.3 *.4 C1_1.1 C1_1.2 C1_2.1 C1_2.2 C1_3.1 C1_3.2 C2_1.1 C2_1.2 C2_2.1 C2_2.2 C2_3.1 C2_3.2 C3_1.1 C3_1.2 C3_2.1 C3_2.2 C4.1 C4.2 C4_1.1 C4_1.2 C5.1 C5.2 C6.1 C6.2 C7.1 C7.2 C8.1 C8.2 C9.1 C9.2 C10.1 C10.2 C11.1 C11.2 C12.1 C12.2 C13.1 C13.2 C14.1 C14.2 C15.1 C15.2 C16.1 C16.2 C17.1 C17.2 C18.1 C18.2 C19.1 C19.2 C20.1 C20.2 C21.1 C21.2 D1_2.1 D1_2.2 D2_1.1 D2_1.2 D3_1.1 D3_1.2 D4_1.1 D4_1.2 D5_1.1 D5_1.2 D6_1.1 D6_1.2 D7_1.1 D7_1.2 D8_1.1 D8_1.2 D9_1.1 D9_1.2 D10_1.1 D10_1.2 L1_1.1 L1_1.2 L2.1 L2.2 L3.1 L3.2 P1.1 P1.2 P1.3 P1.4 P1.5 P1.6 P1.7 P1.8 P1_1.1 P1_1.2 P1_1.3 P1_1.4 P1_1.5 P1_1.6 P1_1.7 P1_1.8 P1_1.9 P1_1.10 P1_1.11 P1_1.12 P1_1.13 P1_1.14 P1_1.15 P1_1.16 P1_1.17 P1_1.18 P1_1.19 P1_1.20 P1_2.1 P1_2.2 P1_3.1 P1_3.2 P1_3.3 P1_3.4 P1_3.5 P1_3.6 P1_4.1 P1_4.2 P1_5.1 P1_5.2 P1_5.3 P1_5.4 P1_5.5 P1_5.6 P1_5.7 P1_5.8 P1_5.9 P1_5.10 P1_5.11 P1_5.12 P2.1 P2.2 P2.3 P2.4 P2.5 P2.6 P2.7 P2.8 P2_1.1 P2_1.2 P2_1.3 P2_1.4 P2_1.5 P2_1.6 P2_1.7 P2_1.8 P2_1.9 P2_1.10 P2_1.11 P2_1.12 P2_1.13 P2_1.14 P2_1.15 P2_1.16 P2_1.17 P2_1.18 P2_1.19 P2_1.20 P2_2.1 P2_2.2 P2_2.3 P2_2.4 P2_2.5 P2_2.6 P2_3.1 P2_3.2 P2_4.1 P2_4.2 P2_5.1 P2_5.2 P2_5.3 P2_5.4 P2_5.5 P2_5.6 P2_5.7 P2_5.8 P2_5.9 P2_5.10 P2_5.11 P2_5.12 P3.1 P3.2 P3.3 P3.4 P3.5 P3.6 P3.7 P3.8 P3_1.1 P3_1.2 P3_1.3 P3_1.4 P3_1.5 P3_1.6 P3_1.7 P3_1.8 P3_1.9 P3_1.10 P3_1.11 P3_1.12 P3_1.13 P3_1.14 P3_1.15 P3_1.16 P3_1.17 P3_1.18 P3_1.19 P3_1.20 P3_2.1 P3_2.2 P3_3.1 P3_3.2 P3_4.1 P3_4.2 P3_5.1 P3_5.2 P3_5.3 P3_5.4 P3_5.5 P3_5.6 P3_5.7 P3_5.8 P3_5.9 P3_5.10 P3_5.11 P3_5.12 P4.1 P4.2 P4.3 P4.4 P4.5 P4.6 P4.7 P4.8 P4_1.1 P4_1.2 P4_1.3 P4_1.4 P4_1.5 P4_1.6 P4_1.7 P4_1.8 P4_1.9 P4_1.10 P4_1.11 P4_1.12 P4_1.13 P4_1.14 P4_1.15 P4_1.16 P4_1.17 P4_1.18 P4_1.19 P4_1.20 P4_2.1 P4_2.2 P4_3.1 P4_3.2 P4_4.1 P4_4.2 P4_4.3 P4_4.4 P4_4.5 P4_4.6 P4_4.7 P4_4.8 P4_4.9 P4_4.10 P4_4.11 P4_4.12 P5.1 P5.2 P5.3 P5.4 P5.5 P5.6 P5.7 P5.8 P5_1.1 P5_1.2 P5_1.3 P5_1.4 P5_1.5 P5_1.6 P5_1.7 P5_1.8 P5_1.9 P5_1.10 P5_1.11 P5_1.12 P5_1.13 P5_1.14 P5_1.15 P5_1.16 P5_1.17 P5_1.18 P5_1.19 P5_1.20 P5_2.1 P5_2.2 P5_2.3 P5_2.4 P5_2.5 P5_2.6 P5_2.7 P5_2.8 P5_2.9 P5_2.10 P5_2.11 P5_2.12 P6.1 P6.2 P6.3 P6.4 P6.5 P6.6 P6.7 P6.8 P6_1.1 P6_1.2 P6_1.3 P6_1.4 P6_1.5 P6_1.6 P6_1.7 P6_1.8 P6_1.9 P6_1.10 P6_1.11 P6_1.12 P6_1.13 P6_1.14 P6_1.15 P6_1.16 P6_1.17 P6_1.18 P6_1.19 P6_1.20 P6_2.1 P6_2.2 P6_2.3 P6_2.4 P6_2.5 P6_2.6 P6_2.7 P6_2.8 P6_2.9 P6_2.10 P6_2.11 P6_2.12 P7.1 P7.2 P7.3 P7.4 P7.5 P7.6 P7.7 P7.8 P7_1.1 P7_1.2 P7_1.3 P7_1.4 P7_1.5 P7_1.6 P7_1.7 P7_1.8 P7_1.9 P7_1.10 P7_1.11 P7_1.12 P7_1.13 P7_1.14 P7_1.15 P7_1.16 P7_1.17 P7_1.18 P7_1.19 P7_1.20 P7_2.1 P7_2.2 P8.1 P8.2 P8.3 P8.4 P8.5 P8.6 P8.7 P8.8 P8_1.1 P8_1.2 P8_1.3 P8_1.4 P8_1.5 P8_1.6 P8_1.7 P8_1.8 P8_1.9 P8_1.10 P8_1.11 P8_1.12 P8_1.13 P8_1.14 P8_1.15 P8_1.16 P8_1.17 P8_1.18 P8_1.19 P8_1.20 P8_2.1 P8_2.2 P9.1 P9.2 P9.3 P9.4 P9.5 P9_1.1 P9_1.2 P9_1.3 P9_1.4 P9_1.5 P9_1.6 P9_1.7 P9_1.8 P9_1.9 P9_1.10 P9_1.11 P9_1.12 P9_1.13 P9_1.14 P9_1.15 P9_1.16 P9_1.17 P9_1.18 P9_1.19 P9_1.20 P9_2.1 P9_2.2 P10.1 P10.2 P10.3 P10.4 P10.5 P10.6 P10.7 P10.8 P10.9 P10.10 P10.11 P10.12 P10.13 P10.14 P10.15 P10.16 P10.17 P10.18 P10_1.1 P10_1.2 P10_1.3 P10_1.4 P10_1.5 P10_1.6 P10_1.7 P10_1.8 P10_1.9 P10_1.10 P10_1.11 P10_1.12 P10_1.13 P10_1.14 P10_1.15 P10_1.16 P10_1.17 P10_1.18 P10_1.19 P10_1.20 P10_2.1 P10_2.2 P11.1 P11.2 P11.3 P11.4 P11.5 P11.6 P11.7 P11.8 P11_1.1 P11_1.2 P11_1.3 P11_1.4 P11_1.5 P11_1.6 P11_1.7 P11_1.8 P11_1.9 P11_1.10 P11_1.11 P11_1.12 P11_1.13 P11_1.14 P11_1.15 P11_1.16 P11_1.17 P11_1.18 P11_1.19 P11_1.20 P11_2.1 P11_2.2 P12.1 P12.2 P12.3 P12.4 P12.5 P12_1.1 P12_1.2 P12_1.3 P12_1.4 P12_1.5 P12_1.6 P12_1.7 P12_1.8 P12_1.9 P12_1.10 P12_1.11 P12_1.12 P12_1.13 P12_1.14 P12_1.15 P12_1.16 P12_1.17 P12_1.18 P12_1.19 P12_1.20 P12_2.1 P12_2.2 P13.1 P13.2 P13.3 P13.4 P13.5 P13.6 P13.7 P13.8 P13_1.1 P13_1.2 P13_1.3 P13_1.4 P13_1.5 P13_1.6 P14.1 P14.2 P14.3 P14.4 P14.5 P14.6 P15.1 P15.2 P15.3 P15.4 P15.5 P15.6 P16.1 P16.2 P16.3 P16.4 P16.5 P16.6 P17.1 P17.2 P17.3 P17.4 P17.5 P17.6 P18.1 P18.2 P18.3 P18.4 P18.5 P18.6 P19.1 P19.2 P19.3 P19.4 P19.5 P19.6 P20.1 P20.2 P20.3 R1_1.1 R1_1.2 R1_2.1 R1_2.2 R1_3.1 R1_3.2 R1_4.1 R1_4.2 R1_5.1 R1_5.2 R2_1.1 R2_1.2 R2_2.1 R2_2.2 R2_3.1 R2_3.2 R2_4.1 R2_4.2 R3_1.1 R3_1.2 R3_2.1 R3_2.2 R3_3.1 R3_3.2 R4_1.1 R4_1.2 R4_2.1 R4_2.2 R4_3.1 R4_3.2 R5_1.1 R5_1.2 R5_2.1 R5_2.2 R5_3.1 R5_3.2 R6_1.1 R6_1.2 R6_2.1 R6_2.2 R6_3.1 R6_3.2 R7.1 R7.2 R7_1.1 R7_1.2 R8.1 R8.2 R8_1.1 R8_1.2 R9.1 R9.2 R9_1.1 R9_1.2 R10.1 R10.2 R10_1.1 R10_1.2 R11.1 R11.2 R11_1.1 R11_1.2 R12.1 R12.2 R12_1.1 R12_1.2 R13.1 R13.2 R13_1.1 R13_1.2 R14.1 R14.2 R14_1.1 R14_1.2 R15.1 R15.2 R15_1.1 R15_1.2 R16.1 R16.2 R17.1 R17.2 R18.1 R18.2 R19.1 R19.2 R20.1 R20.2 R21.1 R21.2 R22.1 R22.2 R23.1 R23.2 R24.1 R24.2 R25.1 R25.2 R26.1 R26.2 R27.1 R27.2 R28.1 R28.2 R29.1 R29.2 R30.1 R30.2 R31.1 R31.2 R32.1 R32.2 R33.1 R33.2 R34.1 R34.2 R35.1 R35.2 R36.1 R36.2 R37.1 R37.2 R38.1 R38.2 R39.1 R39.2 R40.1 R40.2 R41.1 R41.2 R42.1 R42.2 R43.1 R43.2 R44.1 R44.2 R45.1 R45.2 R46.1 R46.2 R47.1 R47.2 R48.1 R48.2 R49.1 R49.2 R50.1 R50.2 R51.1 R51.2 R52.1 R52.2 R53.1 R53.2 R54.1 R54.2 R55.1 R55.2 R56.1 R56.2 R57.1 R57.2 R58.1 R58.2 R59.1 R59.2 R60.1 R60.2 R61.1 R61.2 R62.1 R62.2 R63.1 R63.2 R64.1 R64.2 T1.1 T2.1 T3.1 T4.1 T5.1 T6.1 T7.1 T8.1 T9.1 T10.1 T11.1 T12.1 T13.1 TP1.1 TP2.1 TP3.1 TP4.1 U1.1 U1.2 U1.3 U1.4 U1.5 U1.6 U1.7 U1.8 U1.9 U1.10 U1.11 U1.12 U1.13 U1.14 U1.15 U1.16 U1.17 U1.18 U1.19 U1.20 U1.21 U1.22 U1.23 U1.24 U1.25 U1.26 U1.27 U1.28 U1.29 U1.30 U1.31 U1.32 U1.33 U1.34 U1.35 U1.36 U1.37 U1.38 U1.39 U1.40 U1_1.1 U1_1.2 U1_1.3 U1_1.4 U1_1.5 U1_1.6 U1_1.7 U1_1.8 U1_1.9 U1_1.10 U1_1.11 U1_1.12 U1_1.13 U1_1.14 U1_1.15 U1_1.16 U?_1.1 U?_1.2 U?_1.3 U?_1.4 U?_1.5 U?_1.6 U?_1.7 U?_1.8 U?_1.9 U?_1.10 U?_1.11 U?_1.12 U?_1.13 U?_1.14 U?_1.15 U?_1.16 U?_1.17 U?_1.18 U?_1.19 U?_1.20 U?_1.21 U?_1.22 U?_1.23 U?_1.24 U?_1.25 U?_1.26 U?_1.27 U?_1.28 U?_1.29 U?_1.30 U?_1.31 U?_1.32 U?_1.33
